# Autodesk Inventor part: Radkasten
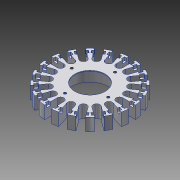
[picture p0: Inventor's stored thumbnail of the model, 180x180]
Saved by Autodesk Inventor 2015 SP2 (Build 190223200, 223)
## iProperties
Created: 2012-07
Part Number: Radkasten
Material: Aluminium 6061
Document SubType Name: Modeling
Designer: rYan
Density: 2.71 g/cm^3
Mass: 19.7681 g
Surface Area: 71.5923 cm^2
Volume: 7.29451 cm^3
Appearance: Aluminium - flach
Author: rYan
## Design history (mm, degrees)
sketch "Skizze1"
  geometry: C1 r 25 at (0, 0); 1 further point
  constraints: 1 centre point, 1 coincident
  dimensions: "d0" = 50 diameter of C1
extrude "Extrusion1" new body sketch "Skizze1" distance "d2" = 7.5; taper "d3" = 0 deg
sketch "Skizze2"
  geometry: L1 (-2, 25)-(2, 25); L2 (2, 25)-(2, 17.5); L3 (-2, 25)-(-2, 17.5); L4 (0, 35)-(0, -35) reference; C1 r 15.5 at (0, 0); C2 r 25 at (0, 0) reference; A1 r 2 centre (0, 17.5) between (-2, 17.5) and (2, 17.5); 1 further point
  constraints: 6 end point, 4 tangent, 2 centre point, 2 point on circle, 1 coincident, 1 parallel, 1 perpendicular, 1 other
  dimensions: "d4" = 31 diameter of C1; "d6" = 4 distance between parallel lines of L2 L3
extrude "Extrusion2" cut sketch "Skizze2" stored distance "d7" = 8; taper "d8" = 0 deg
sketch "Skizze3"
  geometry: L1 (0, 35)-(0, -35) reference; L2 (-3.05, 23.55)-(3.05, 23.55); L3 (3.05, 21.45)-(-3.05, 21.45); L4 (3.05, 22.5)-(-3.05, 22.5); L5 (3.05, 23.55)-(3.05, 21.45); L6 (-3.05, 23.55)-(-3.05, 21.45); A1 r 25 centre (0, 0) between (-2, 24.92) and (2, 24.92) reference; A2 r 25 centre (0, 0) between (2, 24.92) and (-2, 24.92); 2 further points
  constraints: 10 end point, 3 point on circle, 2 parallel, 2 symmetric about line, 1 centre point, 1 concentric, 1 midpoint, 1 perpendicular, 2 other
  dimensions: "d13" = 6.1 distance of L4.start L4.end; "d14" = 2.1 distance between parallel lines of L3 L2; "d43" = 2.5 distance from line of L4 point (0, 25)
extrude "Extrusion3" cut sketch "Skizze3" distance "d15" = 2; taper "d16" = 0 deg
sketch "Skizze4"
  geometry: 1 further point
hole "Bohrung1" sketch "Skizze4" at (0, 0) diameter "d17" = 18; stored, may be unused: countersink angle "d21" = 90 deg, drill point angle "d23" = 118 deg; dims "d18" = 6, "d19" = 4, "d20" = 2, "d22" = 8
sketch "Skizze5"
  geometry: 1 further point
hole "Bohrung2" sketch "Skizze5" at (0, 0) diameter "d24" = 22; stored, may be unused: countersink angle "d28" = 90 deg, drill point angle "d30" = 0 deg; dims "d25" = 6, "d26" = 4, "d27" = 2, "d29" = 7
sketch "Skizze6" dims "d31" = 46
  geometry: L1 (0, -35)-(0, 35) reference; L2 (0, 0)-(3.598, -22.717); L3 (-35, 0)-(35, 0) reference; 1 further point
  constraints: 2 end point, 1 coincident, 3 other
  dimensions: "d73" = 9 deg angle of L2 L1
hole "Bohrung3" sketch "Skizze6" at (3.598, -22.717) diameter "d33" = 1.99; stored, may be unused: countersink angle "d37" = 90 deg, drill point angle "d39" = 118 deg; dims "d34" = 6, "d35" = 4, "d36" = 2, "d38" = 3
pattern_circular "Runde Anordnung2" dims angle "d41" = 360 deg
sketch "Skizze7" dims "d62" = 26
  geometry: L1 (0, 35)-(0, -35) reference; L2 (-35, 0)-(35, 0) reference; L3 (-2.034, -12.84)-(0, 0); 1 further point
  constraints: 2 end point, 1 coincident, 3 other
  dimensions: "d63" = 9 deg angle of L1 L3
hole "Bohrung4" sketch "Skizze7" at (-2.034, -12.84) diameter "d45" = 1.567; stored, may be unused: countersink angle "d49" = 90 deg, drill point angle "d51" = 118 deg; dims "d46" = 6, "d47" = 4, "d48" = 2, "d50" = 5
pattern_circular "Runde Anordnung3" dims angle "d53" = 360 deg
node "Volumenkörper1"
pattern_circular "Runde Anordnung1" dims angle "d10" = 360 deg
